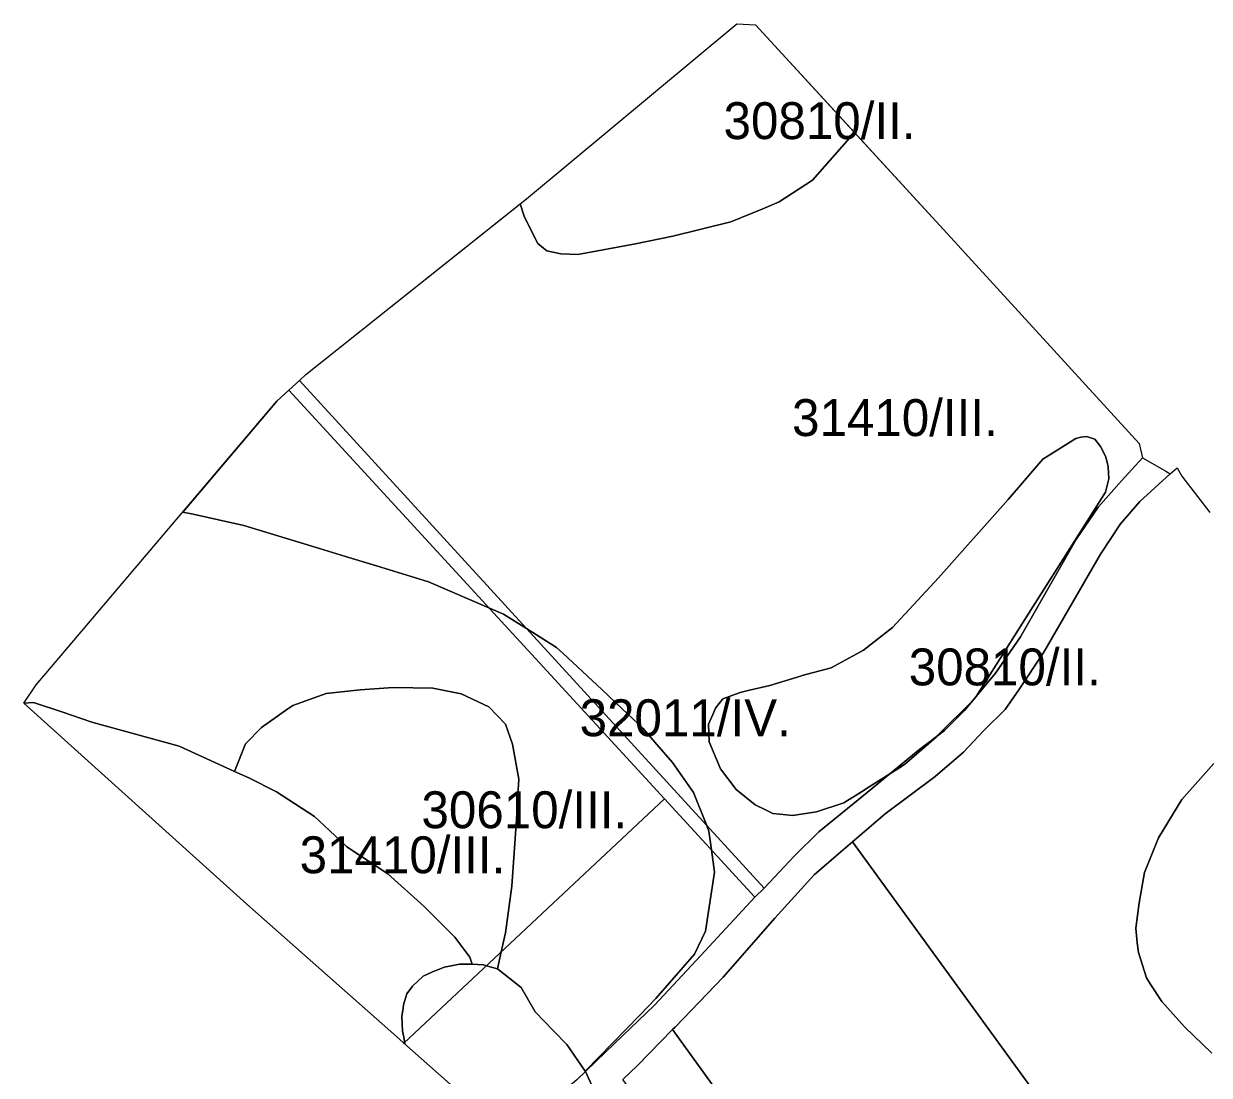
# Model space of a CAD drawing. Extents: x -522079 to -518792, y -1142400 to -1139961.
# Drawn here: x -522079.2 to -521597.2, y -1140463.4 to -1140035.9 of the extents above; entities that cross this region are included whole.
import ezdxf

# ---------------------------------------------------------------- set-up
doc = ezdxf.new("R2010")
doc.units = 0
for name, color, linetype in [('Hranice parcel', 7, 'Continuous'), ('Parcelní čísla', 7, 'Continuous'), ('Značky bodu BP', 7, 'Continuous')]:
    doc.layers.add(name, color=color, linetype=linetype)

msp = doc.modelspace()

# ---------------------------------------------------------------- linework, layer by layer
at = {"layer": 'Hranice parcel'}
msp.add_lwpolyline([(-521854.3, -1140465.27), (-521839, -1140450.48), (-521822.79, -1140434.86), (-521803.88, -1140414.74), (-521781.95, -1140390.97), (-521778.1, -1140387.34), (-521765.79, -1140374.26), (-521755.99, -1140364.38), (-521736.25, -1140348.4), (-521715.5, -1140331.4), (-521704.79, -1140323.18), (-521696.71, -1140315.1), (-521684.15, -1140299.89), (-521673.96, -1140285.19), (-521651.12, -1140245.38), (-521642.31, -1140232.52), (-521632.85, -1140221.77), (-521624.31, -1140212.38), (-521620.19, -1140214.77), (-521614.87, -1140217.86), (-521613.09, -1140218.9), (-521625.36, -1140230.13), (-521633.25, -1140239.25), (-521641.46, -1140251.62), (-521664.44, -1140291.34), (-521674.58, -1140306.67), (-521680.22, -1140314.66), (-521688.85, -1140323.27), (-521697.12, -1140332.11), (-521708.67, -1140341.98), (-521728.93, -1140357.06), (-521742.3, -1140368.5), (-521747.91, -1140373.33), (-521757.78, -1140381.98), (-521773.82, -1140399.6), (-521794.87, -1140423.48), (-521814.39, -1140443.83), (-521815.4, -1140444.86), (-521829.77, -1140459.58), (-521835.62, -1140465.09)], dxfattribs=at)
at = {"layer": 'Parcelní čísla'}
for points in [[(-521755.99, -1140364.38), (-521765.79, -1140374.26), (-521778.1, -1140387.34), (-521967.11, -1140180.95), (-521964.54, -1140178.59), (-521874.73, -1140107.13), (-521789.25, -1140035.92), (-521781.62, -1140036.36), (-521703.78, -1140121.15), (-521625.65, -1140206.61), (-521624.31, -1140212.38), (-521632.85, -1140221.77), (-521642.31, -1140232.52), (-521651.12, -1140245.38), (-521673.96, -1140285.19), (-521684.15, -1140299.89), (-521696.71, -1140315.1), (-521704.79, -1140323.18), (-521715.5, -1140331.4), (-521736.25, -1140348.4)], [(-521971.46, -1140184.95), (-521967.11, -1140180.95), (-521778.1, -1140387.34), (-521781.95, -1140390.97), (-521818.63, -1140351.09)], [(-521926.43, -1140448.75), (-521988.52, -1140393.86), (-522079.24, -1140312.2), (-522074.19, -1140304.73), (-522070.23, -1140300.06), (-521976.31, -1140189.41), (-521971.46, -1140184.95), (-521818.63, -1140351.09), (-521924.65, -1140450.32)], [(-521924.65, -1140450.32), (-521818.63, -1140351.09), (-521781.95, -1140390.97), (-521803.88, -1140414.74), (-521822.79, -1140434.86), (-521839, -1140450.48), (-521854.3, -1140465.27), (-521876.66, -1140484.09), (-521882.18, -1140488.56), (-521891.73, -1140479.43)], [(-521747.91, -1140373.33), (-521742.3, -1140368.5), (-521638.02, -1140511.86), (-521697.45, -1140535.57), (-521738.18, -1140551.68), (-521815.4, -1140444.86), (-521814.39, -1140443.83), (-521794.87, -1140423.48), (-521773.82, -1140399.6), (-521757.78, -1140381.98)], [(-521829.77, -1140459.58), (-521815.4, -1140444.86), (-521738.18, -1140551.68), (-521764.87, -1140562.24), (-521835.62, -1140465.09)]]:
    msp.add_lwpolyline(points, close=True, dxfattribs=at)
msp.add_lwpolyline([(-521592.51, -1140508.64), (-521606.9, -1140511.13), (-521606.6, -1140521.1), (-521611.18, -1140517.57), (-521625.07, -1140510.37), (-521636.41, -1140511.21), (-521638.02, -1140511.86), (-521742.3, -1140368.5), (-521728.93, -1140357.06), (-521708.67, -1140341.98), (-521697.12, -1140332.11), (-521688.85, -1140323.27), (-521680.22, -1140314.66), (-521674.58, -1140306.67), (-521664.44, -1140291.34), (-521641.46, -1140251.62), (-521633.25, -1140239.25), (-521625.36, -1140230.13), (-521613.09, -1140218.9), (-521610.22, -1140216.5), (-521608.33, -1140219.87), (-521596.95, -1140234.61)], dxfattribs=at)
at = {"layer": 'Značky bodu BP'}
for points in [[(-521781.62, -1140036.36), (-521741.42, -1140080.14), (-521758.57, -1140099.56), (-521772.02, -1140108.33), (-521778.76, -1140111.12), (-521791.65, -1140116.47), (-521815.34, -1140122.25), (-521830.49, -1140125.46), (-521853.96, -1140129.74), (-521860.79, -1140129.52), (-521866.55, -1140128.24), (-521867.94, -1140127.1), (-521870.18, -1140125.25), (-521873.59, -1140118.61), (-521875.75, -1140114.18), (-521877.32, -1140109.19), (-521874.73, -1140107.13), (-521789.25, -1140035.92)], [(-522070.23, -1140300.06), (-521976.31, -1140189.41), (-522014.56, -1140234.48), (-522010.4, -1140235.32), (-521989.67, -1140239.88), (-521958.99, -1140249.25), (-521948.36, -1140252.5), (-521935.79, -1140256.37), (-521914.67, -1140262.86), (-521890.13, -1140273.36), (-521884.13, -1140275.92), (-521874.73, -1140281.82), (-521862.58, -1140289.44), (-521859.94, -1140291.89), (-521844.16, -1140306.56), (-521835.9, -1140314.4), (-521827.55, -1140322.33), (-521821.85, -1140328.89), (-521815.42, -1140336.29), (-521806.89, -1140348.46), (-521801.63, -1140361.65), (-521800.6, -1140364.23), (-521799.58, -1140371.8), (-521798.35, -1140380.9), (-521801.95, -1140404.77), (-521806.44, -1140414.24), (-521822.16, -1140432.26), (-521828.66, -1140438.92), (-521850.92, -1140461.73), (-521858.38, -1140450.93), (-521863.76, -1140445.35), (-521871.21, -1140437.63), (-521877.01, -1140427.67), (-521886.61, -1140420.14), (-521885.07, -1140413.27), (-521883.33, -1140405.55), (-521880.75, -1140386.5), (-521878.87, -1140359.44), (-521878.31, -1140349.52), (-521877.94, -1140342.97), (-521880.52, -1140328.85), (-521883.33, -1140320.62), (-521890.13, -1140313.57), (-521901.39, -1140308.39), (-521906.04, -1140307.43), (-521912.88, -1140306.03), (-521929.06, -1140305.8), (-521942.43, -1140306.74), (-521956.27, -1140308.15), (-521969.87, -1140313.09), (-521971.83, -1140314.47), (-521982.54, -1140322.03), (-521989.1, -1140328.62), (-521993.56, -1140339.91), (-522016.02, -1140329.67), (-522051.48, -1140319.82), (-522063.39, -1140315.84), (-522075.3, -1140311.87), (-522079.24, -1140312.2), (-522074.19, -1140304.73)], [(-521771.83, -1140357.25), (-521766.66, -1140357.81), (-521756.91, -1140356.37), (-521745.74, -1140352.63), (-521737.49, -1140347.46), (-521736.56, -1140346.88), (-521727.1, -1140340.91), (-521723.86, -1140338.86), (-521721.09, -1140337.1), (-521708.19, -1140325.89), (-521707.75, -1140325.45), (-521693.23, -1140310.89), (-521692.43, -1140310.08), (-521691.97, -1140309.36), (-521671.5, -1140277.01), (-521649.44, -1140242.23), (-521639.4, -1140226.41), (-521637.97, -1140220.95), (-521638.26, -1140216.07), (-521638.75, -1140214.2), (-521639.4, -1140211.75), (-521641.41, -1140207.73), (-521643.7, -1140204.85), (-521647.14, -1140203.7), (-521649.44, -1140203.99), (-521651.44, -1140204.56), (-521664.91, -1140212.9), (-521678.96, -1140229.29), (-521707.33, -1140261.2), (-521725.96, -1140281.33), (-521737.71, -1140290.53), (-521750.89, -1140297.72), (-521762.65, -1140300.88), (-521763.4, -1140301.11), (-521775.83, -1140304.91), (-521784.1, -1140306.88), (-521787.87, -1140307.78), (-521795.03, -1140310.36), (-521797.9, -1140314.1), (-521799.03, -1140316.71), (-521800.76, -1140320.72), (-521800.48, -1140327.91), (-521795.89, -1140338.83), (-521789.59, -1140347.17), (-521781.85, -1140353.5), (-521777.62, -1140355.53), (-521774.68, -1140356.94)], [(-521756.91, -1140356.37), (-521766.66, -1140357.81), (-521771.83, -1140357.25), (-521774.68, -1140356.94), (-521777.62, -1140355.53), (-521781.85, -1140353.5), (-521789.59, -1140347.17), (-521795.89, -1140338.83), (-521800.48, -1140327.91), (-521800.76, -1140320.72), (-521799.03, -1140316.71), (-521797.9, -1140314.1), (-521795.03, -1140310.36), (-521787.87, -1140307.78), (-521784.1, -1140306.88), (-521775.83, -1140304.91), (-521763.4, -1140301.11), (-521762.65, -1140300.88), (-521750.89, -1140297.72), (-521737.71, -1140290.53), (-521725.96, -1140281.33), (-521707.33, -1140261.2), (-521678.96, -1140229.29), (-521664.91, -1140212.9), (-521651.44, -1140204.56), (-521649.44, -1140203.99), (-521647.14, -1140203.7), (-521643.7, -1140204.85), (-521641.41, -1140207.73), (-521639.4, -1140211.75), (-521638.75, -1140214.2), (-521638.26, -1140216.07), (-521637.97, -1140220.95), (-521639.4, -1140226.41), (-521649.44, -1140242.23), (-521671.5, -1140277.01), (-521691.97, -1140309.36), (-521692.43, -1140310.08), (-521693.23, -1140310.89), (-521707.75, -1140325.45), (-521708.19, -1140325.89), (-521721.09, -1140337.1), (-521723.86, -1140338.86), (-521727.1, -1140340.91), (-521736.56, -1140346.88), (-521737.49, -1140347.46), (-521745.74, -1140352.63)], [(-521885.07, -1140413.27), (-521886.61, -1140420.14), (-521891.03, -1140418.85), (-521892.24, -1140418.49), (-521896.93, -1140418.26), (-521897.87, -1140415.43), (-521903.97, -1140407.2), (-521916.4, -1140394.73), (-521931.17, -1140381.56), (-521947.83, -1140370.5), (-521954.94, -1140363.87), (-521960.96, -1140358.26), (-521976.44, -1140348.15), (-521987.7, -1140342.5), (-521993.56, -1140339.91), (-521989.1, -1140328.62), (-521982.54, -1140322.03), (-521971.83, -1140314.47), (-521969.87, -1140313.09), (-521956.27, -1140308.15), (-521942.43, -1140306.74), (-521929.06, -1140305.8), (-521912.88, -1140306.03), (-521906.04, -1140307.43), (-521901.39, -1140308.39), (-521890.13, -1140313.57), (-521883.33, -1140320.62), (-521880.52, -1140328.85), (-521877.94, -1140342.97), (-521878.31, -1140349.52), (-521878.87, -1140359.44), (-521880.75, -1140386.5), (-521883.33, -1140405.55)], [(-522079.24, -1140312.2), (-522075.3, -1140311.87), (-522063.39, -1140315.84), (-522051.48, -1140319.82), (-522016.02, -1140329.67), (-521993.56, -1140339.91), (-521987.7, -1140342.5), (-521976.44, -1140348.15), (-521960.96, -1140358.26), (-521954.94, -1140363.87), (-521947.83, -1140370.5), (-521931.17, -1140381.56), (-521916.4, -1140394.73), (-521903.97, -1140407.2), (-521897.87, -1140415.43), (-521896.93, -1140418.26), (-521902.1, -1140418.23), (-521906.13, -1140419.06), (-521908.3, -1140419.5), (-521910.2, -1140420.25), (-521912.98, -1140421.34), (-521916.8, -1140423.09), (-521921.16, -1140427.15), (-521923.47, -1140430.34), (-521924.82, -1140434.72), (-521925.01, -1140436.18), (-521925.45, -1140439.5), (-521925.33, -1140442.55), (-521925.22, -1140445.48), (-521924.74, -1140447.9), (-521924.38, -1140449.7), (-521924.23, -1140450.69), (-521924.65, -1140450.32), (-521926.43, -1140448.75), (-521988.52, -1140393.86)]]:
    msp.add_lwpolyline(points, close=True, dxfattribs=at)
for points in [[(-521845.96, -1140472.52), (-521850.83, -1140461.92), (-521850.92, -1140461.73), (-521828.66, -1140438.92), (-521822.16, -1140432.26), (-521806.44, -1140414.24), (-521801.95, -1140404.77), (-521798.35, -1140380.9), (-521799.58, -1140371.8), (-521800.6, -1140364.23), (-521801.63, -1140361.65), (-521806.89, -1140348.46), (-521815.42, -1140336.29), (-521821.85, -1140328.89), (-521827.55, -1140322.33), (-521835.9, -1140314.4), (-521844.16, -1140306.56), (-521859.94, -1140291.89), (-521862.58, -1140289.44), (-521874.73, -1140281.82), (-521884.13, -1140275.92), (-521890.13, -1140273.36), (-521914.67, -1140262.86), (-521935.79, -1140256.37), (-521948.36, -1140252.5), (-521958.99, -1140249.25), (-521989.67, -1140239.88), (-522010.4, -1140235.32), (-522014.56, -1140234.48), (-521976.31, -1140189.41), (-521971.46, -1140184.95), (-521967.11, -1140180.95), (-521964.54, -1140178.59), (-521877.32, -1140109.19), (-521875.75, -1140114.18), (-521873.59, -1140118.61), (-521870.18, -1140125.25), (-521867.94, -1140127.1), (-521866.55, -1140128.24), (-521860.79, -1140129.52), (-521853.96, -1140129.74), (-521830.49, -1140125.46), (-521815.34, -1140122.25), (-521791.65, -1140116.47), (-521778.76, -1140111.12), (-521772.02, -1140108.33), (-521758.57, -1140099.56), (-521741.42, -1140080.14), (-521703.78, -1140121.15), (-521625.65, -1140206.61), (-521624.31, -1140212.38), (-521620.19, -1140214.77), (-521614.87, -1140217.86), (-521613.09, -1140218.9), (-521610.22, -1140216.5), (-521608.33, -1140219.87), (-521596.95, -1140234.61)], [(-521596.09, -1140454.38), (-521607.23, -1140443.75), (-521616.47, -1140433.39), (-521621.19, -1140426.19), (-521622.73, -1140423.85), (-521625.99, -1140413.49), (-521626.42, -1140409.59), (-521627.07, -1140403.67), (-521625.71, -1140393.32), (-521623.54, -1140381.04), (-521617.83, -1140366.87), (-521608.32, -1140351.33), (-521595.28, -1140336.6)], [(-521595.28, -1140336.6), (-521608.32, -1140351.33), (-521617.83, -1140366.87), (-521623.54, -1140381.04), (-521625.71, -1140393.32), (-521627.07, -1140403.67), (-521626.42, -1140409.59), (-521625.99, -1140413.49), (-521622.73, -1140423.85), (-521621.19, -1140426.19), (-521616.47, -1140433.39), (-521607.23, -1140443.75), (-521596.09, -1140454.38)], [(-521891.73, -1140479.43), (-521924.65, -1140450.32), (-521924.23, -1140450.69), (-521924.38, -1140449.7), (-521924.74, -1140447.9), (-521925.22, -1140445.48), (-521925.33, -1140442.55), (-521925.45, -1140439.5), (-521925.01, -1140436.18), (-521924.82, -1140434.72), (-521923.47, -1140430.34), (-521921.16, -1140427.15), (-521916.8, -1140423.09), (-521912.98, -1140421.34), (-521910.2, -1140420.25), (-521908.3, -1140419.5), (-521906.13, -1140419.06), (-521902.1, -1140418.23), (-521896.93, -1140418.26), (-521892.24, -1140418.49), (-521891.03, -1140418.85), (-521886.61, -1140420.14), (-521877.01, -1140427.67), (-521871.21, -1140437.63), (-521863.76, -1140445.35), (-521858.38, -1140450.93), (-521850.92, -1140461.73), (-521850.83, -1140461.92), (-521845.96, -1140472.52)]]:
    msp.add_lwpolyline(points, dxfattribs=at)

# ---------------------------------------------------------------- texts
for s, rotation, p in [('30810/II.', 0, (-521794.68, -1140082.83)), ('31410/III.', 360, (-521766.82, -1140203.55)), ('30810/II.', 360, (-521719.37, -1140304.9)), ('32011/IV.', 0, (-521853.19, -1140325.57)), ('30610/III.', 360, (-521917.51, -1140362.97)), ('31410/III.', 0, (-521967.04, -1140381.28))]:
    msp.add_text(s, height=15, rotation=rotation, dxfattribs=at).set_placement(p)

doc.saveas('drawing.dxf')
